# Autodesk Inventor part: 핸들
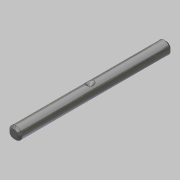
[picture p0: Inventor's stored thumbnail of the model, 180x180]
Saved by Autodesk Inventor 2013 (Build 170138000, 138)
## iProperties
Created: 2019-04
Part Number: 핸들
Material: 스테인리스강
Document SubType Name: Modeling
Designer: mduedu
Density: 1 g/cm^3
Author: mduedu
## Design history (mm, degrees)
sketch "스케치1"
  geometry: C1 r 3 at (0, 0); 1 further point
  constraints: 1 centre point, 1 coincident
  dimensions: "d0" = 6 diameter of C1
extrude "돌출1" new body sketch "스케치1" stored distance "d1" = 74; taper "d2" = 0 deg
chamfer "모따기1" distance "d3" = 1; stored, may be unused: second distance "d4" = 2, angle "d5" = 45 deg
sketch "스케치2"
  geometry: L1 (-36, 3)-(36, 3) reference; L2 (0, 3)-(0, 1); L3 (0, 1)-(2, 3); L4 (0, 3)-(2, 3); 1 further point
  constraints: 6 end point, 2 perpendicular, 1 midpoint, 1 point on line
  dimensions: "d6" = 4 diameter of L3.end L2; "d8" = 45 deg angle of L3 L2
revolve "회전1" sketch "스케치2" stored, may be unused: angle "d10" = 90 deg
node "작업점1"
  node "작업축1"
  node "작업 평면1"
node "솔리드1"
